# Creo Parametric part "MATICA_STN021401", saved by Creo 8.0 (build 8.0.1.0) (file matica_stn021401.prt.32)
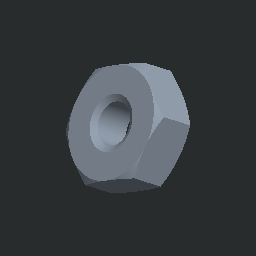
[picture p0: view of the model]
Units: Custom; MM, KILOGRAM, SECS
Materials in the file: OCEL_N

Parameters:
  NAZOV = "MATICA_STN021401"
  NORMA = "STN 02 1401"
  PTC_MATERIAL_NAME = "OCEL_N"

Other parameters: HMOTNOST, HUSTOTA, D12, D19

Created from: C021401.PRT

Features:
  1. datum plane "DTM1"
  2. cut
  3. cut
  4. datum plane "DTM2"
  5. datum plane "DTM3"

Other named items: THRU, S_00034, S_00043, S_00052, S_00054, S_00056, S_00058, S_00060, S_00062, S_00064, S_00066, S_00087, S_00091, S_00105, S_00109, S_00146, S_00148, S_00160, S_00162

Layers: 1, 2, 3, 4, 5, 6, 7, 8, 9, 10, 11, 12, 13, 14, 15, 16, 17, 18, 19, 20, 21, 22, 23, 24, 25, 26, 27, 28, 29, 30, 31, 32, ROVINY

Family table entries: MATICA_M1_6, MATICA_STN021401, value(d_val), value(i_val), MATICA_M2, MATICA_STN021401, MATICA_M2_5, MATICA_STN021401, MATICA_M3, MATICA_STN021401, MATICA_M4, MATICA_STN021401, MATICA_M5, MATICA_STN021401, 2/ , value(s_val), _MATICA_M5, .PRO_MP_CSYS, info(feat_list_rev_info), revision(mdl_geom_rev_detail_t_geomrev), info(tuples_list_rev_info), data(extra_mps), info(geom_item_rev_info), ._MATICA_M5, .PRO_MP_CSYS, MATICA_M6, MATICA_STN021401, 2/$, MATICA_M8, MATICA_STN021401, &/ , 2/*, ._MATICA_M8, .PRO_MP_CSYS, ._MATICA_M8, .PRO_MP_CSYS, MATICA_M8X1, MATICA_STN021401, &/ , 2/*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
